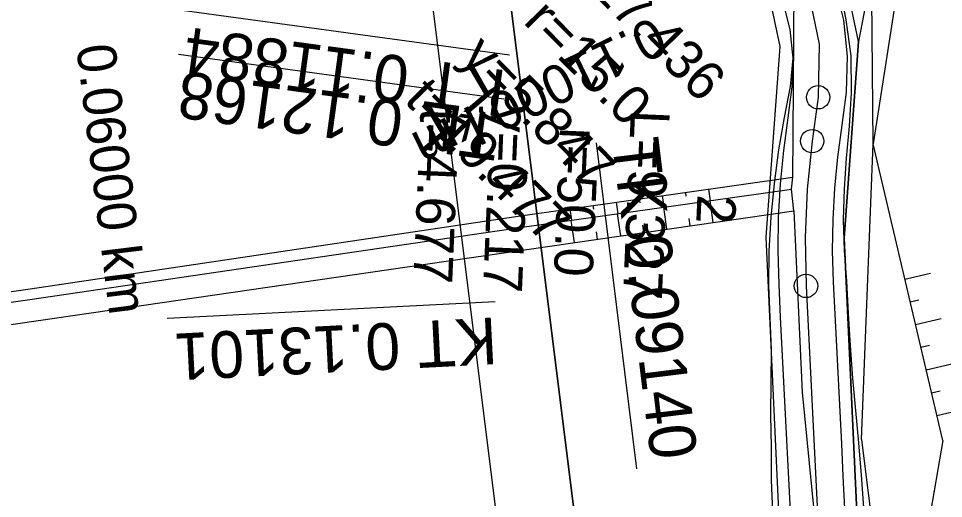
# Model space of a CAD drawing. Extents: x -555887 to -552101, y -1100251 to -1096546.
# Drawn here: x -553981 to -553921.6, y -1097715.1 to -1097684.2 of the extents above; entities that cross this region are included whole.
import ezdxf

# ---------------------------------------------------------------- set-up
doc = ezdxf.new("R2010")
doc.units = 0
for name, color, linetype in [('PARCELY_cesty', 7, 'Continuous'), ('PARCELY_VHO', 7, 'Continuous'), ('POLYGONY_SITUACE_PF_POPISY', 7, 'Continuous'), ('POLYGONY_SITUACE_PO', 7, 'Continuous'), ('ROZHLED_ram_legenda_1', 7, 'Continuous'), ('ZSST', 7, 'Continuous')]:
    doc.layers.add(name, color=color, linetype=linetype)

msp = doc.modelspace()

# ---------------------------------------------------------------- linework, layer by layer
for p, q in [((-553949.423, -1097686.584), (-553970.321, -1097683.733)), ((-553949.807, -1097689.4), (-553970.706, -1097686.549)), ((-553943.857, -1097692.222), (-553941.276, -1097713.156)), ((-553950.359, -1097702.428), (-553971.423, -1097703.502))]:
    msp.add_line(p, q)
at = {"layer": 'PARCELY_cesty'}
for points in [[(-553910.622, -1097956.19), (-553913.42, -1097924.46), (-553903.498, -1097838.889), (-553902.803, -1097824.091), (-553903.199, -1097814.131), (-553905.076, -1097799.369), (-553911.111, -1097775.519), (-553924.494, -1097736.179), (-553926.037, -1097728.701), (-553926.88, -1097721.034), (-553927.942, -1097698.335), (-553927.014, -1097685.697), (-553927.851, -1097681.722), (-553929.538, -1097678.1), (-553932.003, -1097674.954), (-553935.116, -1097672.449), (-553938.716, -1097670.715), (-553942.616, -1097669.842), (-553946.468, -1097669.874), (-554027.52, -1097678.879), (-554030.91, -1097678.33)], [(-553915.615, -1097956.495), (-553918.446, -1097924.391), (-553908.484, -1097838.483), (-553907.808, -1097824.073), (-553908.187, -1097814.546), (-553909.998, -1097800.301), (-553915.909, -1097776.94), (-553929.328, -1097737.494), (-553930.981, -1097729.481), (-553931.867, -1097721.425), (-553932.951, -1097698.268), (-553932.053, -1097686.035), (-553932.625, -1097683.313), (-553933.828, -1097680.732), (-553935.584, -1097678.49), (-553937.803, -1097676.705), (-553940.369, -1097675.469), (-553943.148, -1097674.846), (-553946.14, -1097674.871), (-554026.66, -1097685.902), (-554029.64, -1097687.62)]]:
    msp.add_lwpolyline(points, dxfattribs=at)
at = {"layer": 'PARCELY_VHO'}
msp.add_lwpolyline([(-553927.41, -1097628.08), (-553920.29, -1097651.1), (-553924.15, -1097670.8), (-553927.014, -1097685.697), (-553927.942, -1097698.335), (-553926.88, -1097721.034), (-553926.037, -1097728.701), (-553924.494, -1097736.179), (-553911.111, -1097775.519), (-553905.076, -1097799.369), (-553903.199, -1097814.131), (-553902.803, -1097824.091), (-553903.498, -1097838.889), (-553913.42, -1097924.2), (-553904.91, -1097952.6), (-553904.09, -1097966.52), (-553910.368, -1097974.94), (-553913.828, -1098111.034), (-553912.715, -1098125.988), (-553910.789, -1098134.707), (-553870.98, -1098223.96)], dxfattribs=at)
at = {"layer": 'POLYGONY_SITUACE_PO'}
for p, q in [((-553928.542, -1097682.075), (-553927.98, -1097684.331)), ((-553928.542, -1097682.075), (-553927.98, -1097684.331)), ((-553928.279, -1097681.99), (-553927.837, -1097684.305)), ((-553930.238, -1097682.518), (-553929.533, -1097685.866)), ((-553931.87, -1097683.159), (-553931.426, -1097684.943)), ((-553931.87, -1097683.159), (-553931.426, -1097684.943)), ((-553931.87, -1097683.159), (-553931.426, -1097684.943)), ((-553927.98, -1097684.331), (-553927.734, -1097686.642)), ((-553927.98, -1097684.331), (-553927.734, -1097686.642)), ((-553927.837, -1097684.305), (-553927.498, -1097686.633)), ((-553931.426, -1097684.943), (-553931.232, -1097686.771)), ((-553931.426, -1097684.943), (-553931.232, -1097686.771)), ((-553931.426, -1097684.943), (-553931.232, -1097686.771)), ((-553929.533, -1097685.866), (-553929.606, -1097689.288)), ((-553927.734, -1097686.642), (-553927.812, -1097688.964)), ((-553927.734, -1097686.642), (-553927.812, -1097688.964)), ((-553927.498, -1097686.633), (-553927.493, -1097688.997)), ((-553931.232, -1097686.771), (-553931.409, -1097688.596)), ((-553931.232, -1097686.771), (-553931.294, -1097688.608)), ((-553931.232, -1097686.771), (-553931.294, -1097688.608)), ((-553931.232, -1097686.771), (-553931.232, -1097686.771)), ((-553931.409, -1097688.596), (-553931.797, -1097690.582)), ((-553931.294, -1097688.608), (-553931.554, -1097690.616)), ((-553931.294, -1097688.608), (-553931.554, -1097690.616)), ((-553927.812, -1097688.964), (-553928.086, -1097691.089)), ((-553927.812, -1097688.964), (-553928.086, -1097691.089)), ((-553927.493, -1097688.997), (-553927.605, -1097691.154)), ((-553929.606, -1097689.288), (-553929.99, -1097692.104)), ((-553931.797, -1097690.582), (-553932.15, -1097692.671)), ((-553931.554, -1097690.616), (-553931.827, -1097692.71)), ((-553931.554, -1097690.616), (-553931.827, -1097692.71)), ((-553928.086, -1097691.089), (-553928.352, -1097693.126)), ((-553928.086, -1097691.089), (-553928.352, -1097693.126)), ((-553927.605, -1097691.154), (-553927.813, -1097693.19)), ((-553929.99, -1097692.104), (-553930.315, -1097695.196)), ((-553932.15, -1097692.671), (-553932.427, -1097694.825)), ((-553931.827, -1097692.71), (-553932.042, -1097694.855)), ((-553931.827, -1097692.71), (-553932.042, -1097694.855)), ((-553928.352, -1097693.126), (-553928.552, -1097695.126)), ((-553928.352, -1097693.126), (-553928.552, -1097695.126)), ((-553927.813, -1097693.19), (-553927.942, -1097695.173)), ((-553932.427, -1097694.825), (-553932.636, -1097696.991)), ((-553932.042, -1097694.855), (-553932.169, -1097697.007)), ((-553932.042, -1097694.855), (-553932.169, -1097697.007)), ((-553930.315, -1097695.196), (-553930.446, -1097698.301)), ((-553928.552, -1097695.126), (-553928.671, -1097697.133)), ((-553928.552, -1097695.126), (-553928.671, -1097697.133)), ((-553927.942, -1097695.173), (-553927.988, -1097697.157)), ((-553932.636, -1097696.991), (-553932.772, -1097699.167)), ((-553932.169, -1097697.007), (-553932.195, -1097699.163)), ((-553932.169, -1097697.007), (-553932.195, -1097699.163)), ((-553928.671, -1097697.133), (-553928.696, -1097699.143)), ((-553928.671, -1097697.133), (-553928.696, -1097699.143)), ((-553927.988, -1097697.157), (-553927.937, -1097699.138)), ((-553930.446, -1097698.301), (-553930.385, -1097701.409)), ((-553928.696, -1097699.143), (-553928.645, -1097701.152)), ((-553928.696, -1097699.143), (-553928.645, -1097701.152)), ((-553927.937, -1097699.138), (-553927.79, -1097701.112)), ((-553932.772, -1097699.167), (-553932.796, -1097701.35)), ((-553932.195, -1097699.163), (-553932.141, -1097701.319)), ((-553932.195, -1097699.163), (-553932.141, -1097701.319)), ((-553932.796, -1097701.35), (-553932.714, -1097703.44)), ((-553932.141, -1097701.319), (-553932.035, -1097703.405)), ((-553932.141, -1097701.319), (-553932.035, -1097703.405)), ((-553930.385, -1097701.409), (-553929.374, -1097721.229)), ((-553928.645, -1097701.152), (-553928.54, -1097703.227)), ((-553928.645, -1097701.152), (-553928.54, -1097703.227)), ((-553927.79, -1097701.112), (-553927.671, -1097703.183)), ((-553928.54, -1097703.227), (-553928.433, -1097705.308)), ((-553928.54, -1097703.227), (-553928.433, -1097705.308)), ((-553927.671, -1097703.183), (-553927.551, -1097705.263)), ((-553932.714, -1097703.44), (-553932.633, -1097705.522)), ((-553932.035, -1097703.405), (-553931.929, -1097705.486)), ((-553932.035, -1097703.405), (-553931.929, -1097705.486)), ((-553932.633, -1097705.522), (-553932.653, -1097707.609)), ((-553931.929, -1097705.486), (-553931.823, -1097707.567)), ((-553931.929, -1097705.486), (-553931.823, -1097707.567)), ((-553928.433, -1097705.308), (-553928.327, -1097707.388)), ((-553928.433, -1097705.308), (-553928.327, -1097707.388)), ((-553927.551, -1097705.263), (-553927.389, -1097707.34)), ((-553928.327, -1097707.388), (-553928.221, -1097709.469)), ((-553928.327, -1097707.388), (-553928.221, -1097709.469)), ((-553927.389, -1097707.34), (-553927.209, -1097709.417)), ((-553932.653, -1097707.609), (-553932.658, -1097709.695)), ((-553931.823, -1097707.567), (-553931.717, -1097709.647)), ((-553931.823, -1097707.567), (-553931.717, -1097709.647)), ((-553932.658, -1097709.695), (-553932.619, -1097711.779)), ((-553931.717, -1097709.647), (-553931.611, -1097711.728)), ((-553931.717, -1097709.647), (-553931.611, -1097711.728)), ((-553928.221, -1097709.469), (-553928.115, -1097711.55)), ((-553928.221, -1097709.469), (-553928.115, -1097711.55)), ((-553927.209, -1097709.417), (-553927.019, -1097711.494)), ((-553928.115, -1097711.55), (-553928.009, -1097713.63)), ((-553928.115, -1097711.55), (-553928.009, -1097713.63)), ((-553927.019, -1097711.494), (-553926.84, -1097713.571)), ((-553932.619, -1097711.779), (-553932.614, -1097713.865)), ((-553931.611, -1097711.728), (-553931.504, -1097713.808)), ((-553931.611, -1097711.728), (-553931.504, -1097713.808)), ((-553932.614, -1097713.865), (-553932.539, -1097715.947)), ((-553931.504, -1097713.808), (-553931.398, -1097715.889)), ((-553931.504, -1097713.808), (-553931.398, -1097715.889)), ((-553928.009, -1097713.63), (-553927.903, -1097715.711)), ((-553928.009, -1097713.63), (-553927.903, -1097715.711)), ((-553926.84, -1097713.571), (-553926.699, -1097715.649))]:
    msp.add_line(p, q, dxfattribs=at)
for centre in [(-553929.606, -1097689.288), (-553929.99, -1097692.104), (-553930.385, -1097701.409)]:
    msp.add_circle(centre, 0.75, dxfattribs=at)
at = {"layer": 'ROZHLED_ram_legenda_1'}
msp.add_lwpolyline([(-553930.196, -1097836.542), (-554138.575, -1097862.587), (-554175.41, -1097567.88), (-553967.031, -1097541.835)], close=True, dxfattribs=at)
msp.add_lwpolyline([(-553930.196, -1097836.542), (-554138.575, -1097862.587), (-554175.41, -1097567.88), (-553967.031, -1097541.835)], close=True, dxfattribs=at)
for points in [[(-553967.031, -1097541.835), (-554175.41, -1097567.88), (-554138.575, -1097862.587), (-553930.196, -1097836.542), (-553967.031, -1097541.835)], [(-554134.234, -1097857.005), (-554169.828, -1097572.221), (-553971.373, -1097547.416), (-553935.778, -1097832.201), (-554134.234, -1097857.005)], [(-554134.234, -1097857.005), (-554169.828, -1097572.221), (-553971.373, -1097547.416), (-553935.778, -1097832.201), (-554134.234, -1097857.005)]]:
    msp.add_lwpolyline(points, dxfattribs=at)
at = {"layer": 'ZSST'}
for p, q in [((-553926.08, -1097692.27), (-553926.46, -1097650.16)), ((-553926.81, -1097711.27), (-553926.08, -1097692.27)), ((-553921.6, -1097711.34), (-553926.08, -1097692.27)), ((-553938.134, -1097695.397), (-553938.098, -1097695.646)), ((-553936.648, -1097695.187), (-553936.542, -1097695.936)), ((-553942.589, -1097696.029), (-553942.483, -1097696.774)), ((-553941.104, -1097695.818), (-553941.069, -1097696.067)), ((-553939.619, -1097695.608), (-553939.513, -1097696.355)), ((-553936.347, -1097697.34), (-553936.55, -1097695.937)), ((-553945.559, -1097696.45), (-553945.454, -1097697.193)), ((-553944.074, -1097696.239), (-553944.039, -1097696.487)), ((-553939.316, -1097697.769), (-553939.521, -1097696.356)), ((-553945.255, -1097698.627), (-553945.462, -1097697.194)), ((-553942.286, -1097698.198), (-553942.491, -1097696.775)), ((-553937.832, -1097697.554), (-553937.9, -1097697.086)), ((-553943.77, -1097698.413), (-553943.839, -1097697.937)), ((-553940.801, -1097697.984), (-553940.869, -1097697.511)), ((-553924.037, -1097700.968), (-553922.387, -1097700.581)), ((-553923.694, -1097702.428), (-553923.144, -1097702.299)), ((-553923.351, -1097703.888), (-553921.701, -1097703.501)), ((-553923.008, -1097705.349), (-553922.458, -1097705.22)), ((-553922.664, -1097706.809), (-553921.015, -1097706.421)), ((-553922.321, -1097708.269), (-553921.772, -1097708.14)), ((-553921.978, -1097709.729), (-553920.329, -1097709.342)), ((-553926.81, -1097711.27), (-553924.66, -1097729.04)), ((-553921.6, -1097711.34), (-553924.66, -1097729.04))]:
    msp.add_line(p, q, dxfattribs=at)
for points in [[(-553932.94, -1097613.82), (-553925.77, -1097630.01), (-553920.29, -1097651.1), (-553920.99, -1097659.69), (-553926.08, -1097692.27)], [(-553931.24, -1097694.42), (-553931.2, -1097691.71), (-553931.07, -1097669.67)], [(-554026.48, -1097709.8), (-554014.29, -1097706.49), (-553980.23, -1097701.59), (-553949.02, -1097696.94), (-553931.24, -1097694.42)], [(-553931.16, -1097696.59), (-553931.32, -1097695.2), (-553931.24, -1097694.42)], [(-554026.48, -1097709.8), (-554014.06, -1097707.12), (-553980.24, -1097702.28), (-553948.77, -1097697.66), (-553931.32, -1097695.2)], [(-554016.44, -1097762.67), (-554019.7, -1097743.96), (-554022.62, -1097737.06), (-554025.69, -1097715.06), (-554026.48, -1097709.8), (-553997.95, -1097706.28), (-553954.82, -1097700.01), (-553931.16, -1097696.59)], [(-553931.16, -1097696.59), (-553930.64, -1097708.23), (-553928.64, -1097728.42), (-553922.03, -1097752.14)]]:
    msp.add_lwpolyline(points, dxfattribs=at)

# ---------------------------------------------------------------- texts
for s, height, rotation, p in [('L=27.436', 2.5, 314.62917, (-553946.99, -1097679.724)), ('r=15.0', 2.5, 314.62917, (-553948.612, -1097684.486)), ('KT 0.11884', 3, 172.2311, (-553949.558, -1097687.575)), ('y=5.847', 2.5, 314.62917, (-553952.652, -1097686.799)), ('TK 0.12168', 3, 172.2311, (-553949.942, -1097690.391)), ('t=19.477', 2.5, 314.62917, (-553956.273, -1097689.536)), ('t=4.677', 2.5, 267.57525, (-553955.14, -1097689.964)), ('y=0.217', 2.5, 267.57525, (-553950.629, -1097689.809)), ('L=9.327', 2.5, 267.57525, (-553941.632, -1097690.074)), ('r=50.0', 2.5, 267.57525, (-553946.184, -1097691.19)), ('TK 0.09140', 3, 277.02723, (-553942.864, -1097692.1)), ('2', 2.5, 267.57525, (-553937.359, -1097695.51)), ('KT 0.13101', 3, 182.9194, (-553950.308, -1097703.427))]:
    msp.add_text(s, height=height, rotation=rotation).set_placement(p)
at = {"layer": 'POLYGONY_SITUACE_PF_POPISY'}
for s, rotation, p in [('0.11000 km', 205.98831, (-553940.19, -1097684.062)), ('0.06000 km', 277.02723, (-553977.269, -1097686.016))]:
    msp.add_text(s, height=2.5, rotation=rotation, dxfattribs=at).set_placement(p)

doc.saveas('drawing.dxf')
